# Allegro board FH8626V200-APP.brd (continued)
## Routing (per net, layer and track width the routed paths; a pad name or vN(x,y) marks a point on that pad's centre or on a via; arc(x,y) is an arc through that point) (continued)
CIS_SCL: length 54.2
  TOP w0.102: U14.11 52.02,41.2 51.69,41.53 49.89,41.53 v1(49.86,41.55) ; J3.36 v1(7.48,52.84)
  BOTTOM w0.102: v1(49.86,41.55) 49.63,41.78 R34.2 48.51,42.29 46.56,42.29 46.23,42.62 46.23,43.28 41.78,47.73 12.6,47.73 v1(7.48,52.84)
CIS_SDA: length 54
  TOP w0.102: v1(8.26,52.83) 7.27,51.84 J3.34 ; U14.10 52.18,41.55 51.85,41.88 50.17,41.88 v1(49.78,42.27)
  BOTTOM w0.102: v1(8.26,52.83) 13.03,48.06 41.86,48.06 46.48,43.43 48.51,43.43 R35.2 49.12,42.93 v1(49.78,42.27)
CLK_IN: length 10.8
  TOP w0.203: U14.41 61.05,35.85 61.59,35.3 61.59,27.05 61.09,26.54 R39.2
CLK_OUT: length 11.8
  TOP w0.203: U14.42 61.4,35.97 62,35.36 62,26.39 R40.1 R41.2
DDR_D1.8V: length 9.5
  TOP w0.381: 108.08,35.18 108.08,37.08 108.58,37.59 C27.1 R14.2
DDR_D1.35V: length 10.1
  TOP w0.381: R85.2 C66.1 114.02,31.14 107.72,31.14 107.31,30.73 107.31,28.96
DDR_IO: length 4.2
  TOP w0.178: U14.36 59.3,35.35 59.49,35.15 v1(59.49,34.92) v1(59.94,34.92) ; U14.33 58.24,36.02 57.77,35.55 v1(57.77,35.25) 57.77,34.64 v1(57.78,34.64)
E0_CT1: length 2
  TOP w0.381: U23.2 v1(61.72,65.33)
  BOTTOM w0.381: C165.1 v1(61.72,65.33)
E0_CT2: length 2.1
  TOP w0.381: U23.7 v1(68.07,65.35)
  BOTTOM w0.381: C167.1 v1(68.07,65.35)
EN1: length 25.2
  TOP w0.381: v1(120.02,43.76) 120.02,44.07 121.03,45.09 R13.1
  VCC w0.381: v1(115.82,32.26) 117.47,33.91 v1(117.47,36.96) 117.65,36.96 120.12,39.43 120.12,43.66 v1(120.02,43.76)
  BOTTOM w0.381: R20.1 v1(117.47,36.96) ; R89.1 116.74,29.49 D4.K v1(115.82,32.26) 115.57,32 R19.1 C32.1
EN2: length 5
  TOP w0.381: R12.1 138.79,43.74 v1(139.22,43.74)
  BOTTOM w0.381: D11.K 141.3,44.17 R84.1 C62.1 139.67,44.2 v1(139.22,43.74)
EN3: length 5.5
  BOTTOM w0.381: R27.1 116.84,44.58 116.84,45.75 D5.K 115.57,46.35 115.24,46.02 R22.1 C33.1
EPHY_RXN: length 18.7
  TOP w0.102: U14.67 62.1,46.4 64.01,48.31 64.01,52.32 68.25,56.57 68.25,57.3 68.35,57.4 D32.K 68.36,58.24 68.26,58.34 68.26,58.48 C155.2 68.25,59.13 68.25,59.61 R181.2
EPHY_RXP: length 18.7
  TOP w0.102: R178.2 67.89,59.61 67.89,59.13 C155.1 67.88,58.48 67.88,58.34 D32.A 67.79,57.4 67.89,57.3 67.89,56.71 63.65,52.47 63.65,48.46 61.75,46.55 U14.68
EPHY_TXN: length 16.3
  TOP w0.102: R177.2 61.9,59.61 61.9,59.13 C154.2 61.9,58.47 61.9,58.35 D20.K 62,57.4 61.9,57.3 61.9,47.17 61.4,46.66 U14.69
EPHY_TXP: length 16.3
  TOP w0.102: U14.70 61.05,46.82 61.54,47.32 61.54,57.3 61.44,57.4 D20.A 61.54,58.35 61.54,58.47 C154.1 61.54,59.13 61.54,59.61 R174.2
ETH_ACT: length 22.5
  BOTTOM w0.102: JP4.1 53.76,78.95 70.4,78.95 D19.K 72.01,75.45 J17.12
ETH_STA: length 42.4
  TOP w0.102: v1(50.67,71.88) 50.67,67.11 55.73,62.05 55.73,47.88 56.77,46.84 56.77,46.53 57.19,46.11 U14.81
  BOTTOM w0.102: v1(50.67,71.88) 52.32,73.53 54.74,73.53 55.37,74.17 59.29,74.17 J17.10 60.83,75.71 D23.K
GPIO_0: length 74.9
  TOP w0.102: JP11.2 124.51,54.28 88.6,54.28 72.36,38.05 U14.47
GPIO_1: length 69.7
  TOP w0.102: U14.48 72.25,38.4 88.44,54.58 119.74,54.58 JP12.2
GPIO_2: length 64.4
  TOP w0.102: U14.49 72.15,38.75 88.32,54.91 114.99,54.91 JP7.2
GPIO_3: length 59.8
  TOP w0.102: JP9.2 111.12,56.13 111.12,55.36 111.02,55.25 88.17,55.25 72.01,39.1 64.49,39.1 64.38,38.99 63.68,38.99 63.57,39.1 U14.50
GPIO_4: length 54.1
  TOP w0.102: U14.51 63.68,39.45 63.8,39.32 64.34,39.32 64.47,39.45 71.88,39.45 88.06,55.63 105.54,55.63 JP10.2
GPIO_28: length 34.1
  TOP w0.102: U14.80 57.54,46.44 56.03,47.96 56.03,62.51 55.24,63.3 55.24,74.93 JP4.2
GPIO_RESET: length 70.3
  TOP w0.102: U14.24 55.09,35.95 54.99,35.85 54.99,35.2 54.84,35.05 54.36,35.05 54.18,34.87 54.18,33.45 52.93,32.21 52.93,26.42 53.09,26.26 v1(53.09,25.02) ; v1(102.08,17.86) 103.43,17.86 v1(104.97,16.32)
  VCC w0.102: v1(102.08,17.86) 96.06,17.86 93.52,20.4 65.86,20.4 65.38,19.91 58.55,19.91 53.82,24.64 53.47,24.64 v1(53.09,25.02)
  BOTTOM w0.102: R166.2 104.97,15.81 v1(104.97,16.32)
HOLD: length 48.6
  TOP w0.102: v1(69.98,14.96) 70.21,14.73 U9.7 72.39,14.73 75.69,11.43 78.44,11.43 84.3,5.56 99.8,5.56 101.73,7.49 101.73,8.79 100.72,9.79 U6.7
  BOTTOM w0.102: U10.7 72.24,16 72.42,16.18 72.42,16.48 72.24,16.66 70.33,16.66 70.23,16.56 70.23,15.21 v1(69.98,14.96) 69.62,14.96 69.22,15.37 69.22,16.38
IR_LED_IN: length 3.2
  TOP w0.508: J13.1 v1(7.23,69.48)
  BOTTOM w0.508: 8,70.48 8,69.99 7.49,69.48 v1(7.23,69.48)
IRCUT_OFF: length 152.2
  TOP w0.102: v1(50.29,25.73) v1(8.41,25.73) ; JP10.1 109.88,57.43 109.88,59.94 109.55,60.27 108.25,60.27 103.99,56.01 87.99,56.01 72.06,40.09 71.84,40.09 v1(71.69,39.94) ; v1(74.52,21.31) 82.87,29.66 82.87,37.69 v1(82.2,38.36)
  VCC w0.102: v1(50.29,25.73) 50.65,25.73 50.88,25.96 53.77,25.96 55.4,24.33 62.92,24.33 65.96,21.29 74.5,21.29 v1(74.52,21.31)
  BOTTOM w0.102: v1(82.2,38.36) 81.95,38.61 73.02,38.61 v1(71.69,39.94) ; R144.2 8.38,25.7 v1(8.41,25.73)
IRCUT_ON: length 64.1
  TOP w0.102: U14.25 55.44,35.94 55.27,35.76 55.27,33.81 54.1,32.64 54.1,24.77 53.47,24.13 50.8,24.13 49.71,25.22 5.11,25.22 v1(4.6,25.73)
  BOTTOM w0.102: v1(4.6,25.73) 4.57,25.7 R145.2
IRCUT_OUT_OFF: length 3.3
  TOP w0.508: J15.1 4.56,14.21 v1(4.57,14.22)
  BOTTOM w0.508: U19.4 v1(4.57,14.22)
IRCUT_OUT_ON: length 6.1
  TOP w0.508: J15.2 v1(4.69,12.96)
  BOTTOM w0.508: v1(4.69,12.96) 5.47,12.96 7.11,14.61 U19.2
JTAG_RTCK: length 3.4
  BOTTOM w0.102: R139.1 U18.11
JTAG_SRSTN: length 4.6
  BOTTOM w0.102: U18.15 R141.1 R143.2
LDO_MICBIAS: length 12.3
  VCC w0.381: v1(53.42,16.26) 51.96,17.72 47.56,17.72 v1(47.5,17.65)
  BOTTOM w0.305: R103.2 v1(53.42,16.26)
  BOTTOM w0.381: C112.1 v1(47.5,17.65) C111.1 C110.1 43.82,17.65 43.49,17.97 U11.5
MIPI_CKN: length 47.3
  TOP w0.102: U14.5 53.51,43.3 53.48,43.27 52.74,43.27 52.02,43.99 35.64,43.99 35.13,44.5 25.8,44.5 25.52,44.22 25.52,43.26 25.41,43.15 24.5,43.15 24.4,43.26 24.4,44.22 24.12,44.5 22.95,44.5 22.67,44.22 22.67,43.26 22.57,43.15 21.66,43.15 21.55,43.26 21.55,44.22 21.27,44.5 16.89,44.5 T24.1 16.2,44.5 13.59,44.5 13.25,44.84 J3.19
MIPI_CKP: length 47.3
  TOP w0.102: U14.6 53.5,42.95 53.48,42.97 52.61,42.97 51.89,43.69 35.51,43.69 35.01,44.19 25.92,44.19 25.82,44.09 25.82,43.13 25.54,42.85 24.37,42.85 24.09,43.13 24.09,44.09 23.99,44.19 23.08,44.19 22.98,44.09 22.98,43.13 22.7,42.85 21.53,42.85 21.25,43.13 21.25,44.09 21.15,44.19 16.89,44.19 T23.1 16.2,44.19 13.59,44.19 13.25,43.84 J3.17
MIPI_D5.0V: length 2.7
  TOP w0.381: 14.86,52.84 v1(14.05,52.84) 12.15,52.84
MIPI_DN0: length 47.3
  TOP w0.102: U14.1 53.48,44.7 53.46,44.67 53.32,44.67 51.26,46.74 41.01,46.74 v1(40.84,46.9) ; J3.5 13.25,37.84 13.59,37.5 16.2,37.5 T20.1 16.89,37.5 17.74,37.5 v1(17.9,37.66)
  BOTTOM w0.102: v1(17.9,37.66) 18.07,37.5 30.94,37.5 40.18,46.74 40.68,46.74 v1(40.84,46.9)
MIPI_DN1: length 47.3
  TOP w0.102: U14.4 53.48,43.65 53.46,43.67 52.93,43.67 51.44,45.16 37.55,45.16 37.11,45.6 37.11,46.43 v1(36.94,46.6) ; v1(17.53,40.66) 17.36,40.5 16.89,40.5 T22.1 16.2,40.5 13.59,40.5 13.25,40.84 J3.11
  BOTTOM w0.102: v1(17.53,40.66) 17.69,40.5 31.55,40.5 37.11,46.05 37.11,46.43 v1(36.94,46.6)
MIPI_DP0: length 47.3
  TOP w0.102: v1(17.9,37.03) 17.74,37.19 16.89,37.19 T19.1 16.2,37.19 13.59,37.19 13.25,36.84 J3.3 ; U14.2 53.49,44.35 53.47,44.37 53.19,44.37 51.13,46.43 41.01,46.43 v1(40.84,46.27)
  BOTTOM w0.102: v1(40.84,46.27) 40.68,46.43 40.31,46.43 31.07,37.19 18.07,37.19 v1(17.9,37.03)
MIPI_DP1: length 47.3
  TOP w0.102: v1(37.58,46.6) 37.41,46.43 37.41,45.73 37.68,45.47 51.56,45.47 53.05,43.97 53.47,43.97 53.5,44 U14.3 ; J3.9 13.25,39.84 13.59,40.19 16.2,40.19 T21.1 16.89,40.19 17.36,40.19 v1(17.53,40.03)
  BOTTOM w0.102: v1(37.58,46.6) 37.41,46.43 37.41,45.92 31.68,40.19 17.69,40.19 v1(17.53,40.03)
MOTO_OUT_2: length 9.4
  TOP w0.102: v1(112.39,79.38) 112.39,77.6 112.23,77.43 U26.16 ; R150.1 v1(108.08,80.95)
  BOTTOM w0.102: v1(112.39,79.38) 111.9,79.38 111.16,78.64 109.76,78.64 109.27,79.13 109.27,79.52 108.08,80.72 v1(108.08,80.95)
MOTO_OUT_3: length 7.5
  TOP w0.102: v1(108.92,81.79) 108.92,83.06 109.36,83.5 J19.2 ; U26.2 110.05,79.45 v1(110.11,79.5)
  BOTTOM w0.102: v1(110.11,79.5) 110.11,80.52 108.92,81.71 v1(108.92,81.79)
MOTO_OUT_4: length 6.6
  TOP w0.102: R151.1 109.96,81.79 107.24,79.07 107.24,77.6 107.41,77.43 U26.5
MOTO_OUT_5: length 8.9
  TOP w0.102: J19.4 111.86,80.87 111.51,80.52 109.73,80.52 109.4,80.19 U26.3
MOTO_OUT_6: length 8.4
  TOP w0.102: R152.1 v1(120.78,80.64) ; v1(125.45,78.84) 125.7,78.59 125.7,77.7 125.44,77.43 U27.16
  BOTTOM w0.102: v1(120.78,80.64) 123.65,80.64 v1(125.45,78.84)
MOTO_OUT_7: length 9.4
  TOP w0.102: J20.2 121.93,81.52 v1(122.05,81.41) ; U27.2 123.52,79.57 124.31,80.37 v1(124.31,81.33)
  BOTTOM w0.102: v1(124.31,81.33) 124.28,81.33 124.21,81.41 v1(122.05,81.41)
MOTO_OUT_8: length 5.7
  TOP w0.102: U27.5 120.82,77.43 120.65,77.6 120.65,78.61 123.06,81.03 R153.1
MOTO_OUT_9: length 7.5
  TOP w0.102: U27.3 122.86,79.55 123.66,80.35 123.66,81.32 124.43,82.08 J20.4
NAND_CS: length 24.3
  TOP w0.102: v1(80.9,17.27) 81.92,17.27 82.3,16.89 82.3,14.48 84.2,12.57 v1(84.84,12.57) 89.55,12.57 U6.1
  BOTTOM w0.102: v1(84.84,12.57) 82.55,10.29 JP14.3 ; U10.1 v1(80.9,17.27) 81.03,17.27 R59.2
NOR_CS: length 12.7
  TOP w0.102: v1(80.67,12.95) 80.16,13.46 U9.1
  BOTTOM w0.102: v1(80.67,12.95) 80.92,12.7 R52.2 81.53,12.04 80.92,11.43 74.02,11.43 JP14.1
PHY_RN: length 11.6
  TOP w0.102: U23.9 69.34,73.28 68.2,74.42 68.2,74.96 64.44,78.71 64.44,79.2 64.59,79.35 66.34,79.35 66.65,79.66 J17.6
PHY_RP: length 11.6
  TOP w0.102: U23.11 66.8,73.41 67.84,74.45 67.84,74.81 64.08,78.57 64.08,79.35 63.59,79.84 J17.3
PHY_TN: length 10.7
  TOP w0.102: U23.14 62.99,73.46 61.95,74.5 61.95,77.47 60.91,78.51 60.91,79.93 61.92,80.95 62.26,80.95 62.57,80.64 J17.2
PHY_TP: length 10.7
  TOP w0.102: J17.1 61.55,81.08 60.55,80.08 60.55,78.36 61.59,77.32 61.59,74.55 60.45,73.41 U23.16
PWM11: length 71.6
  TOP w0.102: R108.1 20.55,22.61 22.2,24.26 49.33,24.26 v1(49.63,23.95)
  VCC w0.102: JP22.3 83.31,23.37 64.9,23.37 61.85,26.42 50.34,26.42 49.66,25.73 49.66,23.98 v1(49.63,23.95)
PWM_2: length 68.4
  TOP w0.102: U14.55 71.63,40.85 94,63.22 99.95,63.22 107.64,70.9 111.42,70.9 112.27,71.75 v1(112.27,74.17) ; v1(113.28,74.68) 113.28,75.31 112.47,76.13 U26.14
  BOTTOM w0.102: v1(112.27,74.17) 112.78,74.68 v1(113.28,74.68)
PWM_3: length 67.4
  TOP w0.102: U14.54 71.86,40.5 94.13,62.76 94.23,62.87 100.33,62.87 107.8,70.33 111.73,70.33 112.7,71.3 112.7,74.95 112.17,75.48 U26.13
PWM_4: length 61.4
  TOP w0.102: U14.57 71.13,41.55 93.49,63.92 98.84,63.92 106.43,71.5 106.43,75.34 107.21,76.13 U26.7
PWM_5: length 61.4
  TOP w0.102: U14.56 71.35,41.2 93.72,63.57 99.38,63.57 106.96,71.15 106.96,75.08 107.36,75.48 U26.8
PWM_6: length 22
  TOP w0.102: v1(126.89,67.42) 126.89,75.31 126.07,76.13 U27.14
  BOTTOM w0.102: JP11.1 126.89,58.66 v1(126.89,67.42)
PWM_7: length 20.8
  TOP w0.102: U27.13 125.82,75.48 126.24,75.06 v1(126.24,68.07)
  BOTTOM w0.102: JP12.1 126.24,58.55 v1(126.24,68.07)
PWM_8: length 21.5
  TOP w0.102: U27.7 120.71,76.13 119.95,75.37 119.95,66.23 v1(120.4,65.79)
  BOTTOM w0.102: v1(120.4,65.79) 120.52,65.66 120.52,57.91 JP7.1
PWM_9: length 22.7
  TOP w0.102: U27.8 120.94,75.48 120.65,75.18 v1(120.65,67.06)
  BOTTOM w0.102: v1(120.65,67.06) 120.04,67.06 115.82,62.84 115.82,58.29 JP9.1
RESETN: length 68.3
  TOP w0.102: U14.43 61.75,36.04 62.64,35.15 63.14,35.15 63.75,34.54 v1(63.75,33.02) 63.75,31.01 65.94,28.83 65.94,22.86 v1(66.55,22.25) ; v1(114.55,17.53) 106.55,17.53 105.08,19 v1(102.41,19)
  VCC w0.102: v1(66.55,22.25) 66.57,22.23 79.63,22.23 80.75,21.11 91.16,21.11 91.62,21.56 95.94,21.56 98.5,19 v1(102.41,19)
  BOTTOM w0.102: v1(63.75,33.02) 63.88,33.15 C190.2 ; v1(114.55,17.53) R172.2
RTC_VBAT: length 14.7
  BOTTOM w0.381: R61.1 C102.1 69.47,34.04 68.83,34.67 64.9,34.67
RTC_XIN: length 12.5
  TOP w0.203: U14.45 63.29,37.35 64.44,36.2 72.9,36.2 C79.2 73.46,36 U8.1
RTC_XOUT: length 12.4
  TOP w0.203: U8.4 73.34,36.9 C81.2 73.03,36.7 64.47,36.7 63.47,37.7 U14.46
SD0_3.3V: length 28.8
  TOP w0.381: J4.6 v1(35.26,61.09)
  BOTTOM w0.381: 37.72,62.1 37.29,62.1 36.27,61.09 v1(35.26,61.09) ; 37.72,62.1 R67.1 ; 37.72,62.1 37.47,62.36 37.47,62.87 36.83,63.5 31.62,63.5 30.86,62.74 R82.1 R64.1 R65.1 ; R67.1 C104.1 R74.2 43.69,64.14 MQ1.3 ; R67.1 R66.1
SD0_CD: length 65.6
  TOP w0.102: v1(45.69,62.08) 45.11,62.08 44.93,61.9 34.44,61.9 v1(34.11,61.57) ; U14.88 54.74,45.85 54.47,46.12 53.83,46.12 52.34,47.61 52.34,49.82 51.79,50.37 51.79,52.48 48.95,55.32 46.02,55.32 44.2,53.49 40.39,53.49 40.18,53.7 37.13,53.7 36.8,54.03 36.8,55.55 36.68,55.68 36.23,55.68 36.13,55.58 36.13,54.91 36.03,54.81 35.83,54.81 35.72,54.91 35.72,55.58 35.62,55.68 35.42,55.68 35.32,55.58 35.32,54.91 35.22,54.81 35.01,54.81 34.91,54.91 34.91,55.58 34.81,55.68 34.61,55.68 34.5,55.58 34.5,54.91 34.4,54.81 34.2,54.81 34.1,54.91 34.1,55.58 34,55.68 33.79,55.68 33.69,55.58 33.69,54.91 33.59,54.81 33.39,54.81 33.29,54.91 33.29,55.58 33.18,55.68 32.87,55.68 32.64,55.91 v1(32.64,57.38)
  BOTTOM w0.102: v1(45.69,62.08) 45.69,62.66 46.08,63.04 46.08,64.8 45.47,65.41 45.47,67.56 46.35,68.45 R75.1 ; v1(34.11,61.57) 34.11,59.39 33.66,58.93 R77.1 v1(32.64,57.38)
SD0_CLK: length 37.3
  TOP w0.102: v1(37.72,57.15) 38.15,56.72 38.15,54.53 38.25,54.43 38.46,54.43 38.56,54.53 38.56,55.27 38.66,55.37 38.86,55.37 38.96,55.27 38.96,54.53 39.07,54.43 39.27,54.43 39.37,54.53 39.37,55.27 39.47,55.37 39.67,55.37 39.78,55.27 39.78,54.53 39.88,54.43 40.08,54.43 40.18,54.53 40.18,55.27 40.28,55.37 40.49,55.37 40.59,55.27 40.59,54.53 40.69,54.43 40.89,54.43 41,54.53 41,55.27 41.1,55.37 41.3,55.37 41.4,55.27 41.4,54.53 41.5,54.43 41.71,54.43 41.81,54.53 41.81,55.27 41.91,55.37 42.11,55.37 42.21,55.27 42.21,54.53 42.32,54.43 42.52,54.43 42.62,54.53 42.62,55.27 42.72,55.37 42.93,55.37 43.03,55.27 43.03,54.53 43.13,54.43 43.33,54.43 43.43,54.53 43.43,55.27 43.54,55.37 43.74,55.37 43.84,55.27 43.84,54.53 43.94,54.43 44.15,54.43 44.25,54.53 44.25,55.27 44.35,55.37 45.21,55.37 45.62,55.78 50.01,55.78 52.7,53.09 v1(52.7,50.55)
  BOTTOM w0.102: v1(52.7,50.55) C178.1 R204.1 ; R72.1 v1(37.72,57.15)
SD0_CMD: length 40.6
  TOP w0.102: v1(30.86,57.89) 33.26,57.89 33.36,57.78 33.36,57.2 33.46,57.1 33.67,57.1 33.77,57.2 33.77,57.78 33.87,57.89 34.07,57.89 34.18,57.78 34.18,57.2 34.28,57.1 34.48,57.1 34.58,57.2 34.58,57.78 34.68,57.89 34.89,57.89 34.99,57.78 34.99,57.2 35.09,57.1 35.29,57.1 35.39,57.2 35.39,57.78 35.5,57.89 35.7,57.89 35.8,57.78 35.8,57.2 35.9,57.1 36.11,57.1 36.21,57.2 36.21,57.78 36.31,57.89 38.66,57.89 38.91,57.63 38.91,56.34 39.01,56.24 51.13,56.24 53.65,53.72 53.65,47.88 55.44,46.08 U14.86
  BOTTOM w0.102: R79.1 v1(30.86,57.89)
SD0_DATA_0: length 40.3
  TOP w0.102: v1(41.94,57.89) 39.58,57.89 39.34,57.66 39.34,56.67 39.55,56.46 39.82,56.46 39.92,56.57 39.92,57.18 40.02,57.28 40.23,57.28 40.33,57.18 40.33,56.57 40.43,56.46 40.63,56.46 40.73,56.57 40.73,57.18 40.84,57.28 41.04,57.28 41.14,57.18 41.14,56.57 41.24,56.46 41.44,56.46 41.55,56.57 41.55,57.18 41.65,57.28 41.85,57.28 41.95,57.18 41.95,56.57 42.05,56.46 42.26,56.46 42.36,56.57 42.36,57.18 42.46,57.28 42.66,57.28 42.77,57.18 42.77,56.57 42.87,56.46 43.07,56.46 43.17,56.57 43.17,57.18 43.27,57.28 43.48,57.28 43.58,57.18 43.58,56.57 43.68,56.46 51.44,56.46 54.36,53.54 54.36,53.34 54.25,53.24 54.08,53.24 53.98,53.14 53.98,52.93 54.08,52.83 54.25,52.83 54.36,52.73 54.36,52.53 54.25,52.43 54.08,52.43 53.98,52.33 53.98,52.12 54.08,52.02 54.25,52.02 54.36,51.92 54.36,51.72 54.25,51.61 54.08,51.61 53.98,51.51 53.98,51.31 54.08,51.21 54.25,51.21 54.36,51.11 54.36,50.9 54.25,50.8 54.08,50.8 53.98,50.7 53.98,50.5 54.08,50.39 54.25,50.39 54.36,50.29 54.36,50.09 54.25,49.99 54.08,49.99 53.98,49.89 53.98,49.68 54.08,49.58 54.25,49.58 54.36,49.48 54.36,49.28 54.25,49.18 54.08,49.18 53.98,49.07 53.98,48.87 54.08,48.77 54.25,48.77 54.36,48.67 54.36,48.46 54.25,48.36 54.08,48.36 53.98,48.26 53.98,48.06 54.08,47.96 54.25,47.96 54.36,47.85 54.36,47.57 55.45,46.48 55.45,46.38 55.79,46.03 U14.85
  BOTTOM w0.102: R68.1 41.91,57.94 41.94,57.91 v1(41.94,57.89)
SD0_DATA_1: length 40.2
  TOP w0.102: U14.84 56.14,46.04 55.8,46.38 55.8,46.48 54.66,47.62 54.66,53.73 51.58,56.82 50.7,56.82 50.62,56.9 50.62,57.77 50.5,57.89 50.18,57.89 50.08,57.79 50.08,56.82 49.98,56.72 49.78,56.72 49.68,56.82 49.68,57.79 49.57,57.89 49.37,57.89 49.27,57.79 49.27,56.82 49.17,56.72 48.96,56.72 48.86,56.82 48.86,57.79 48.76,57.89 48.56,57.89 48.46,57.79 48.46,56.82 48.35,56.72 48.15,56.72 48.05,56.82 48.05,57.79 47.95,57.89 47.75,57.89 47.64,57.79 47.64,56.82 47.54,56.72 47.34,56.72 47.24,56.82 47.24,57.79 47.14,57.89 46.93,57.89 46.83,57.79 46.83,56.82 46.73,56.72 46.53,56.72 46.42,56.82 46.42,57.79 46.32,57.89 46.12,57.89 46.02,57.79 46.02,56.82 45.92,56.72 45.71,56.72 45.61,56.82 45.61,57.79 45.51,57.89 45.31,57.89 45.21,57.79 45.21,56.82 45.1,56.72 44.9,56.72 44.8,56.82 44.8,57.79 44.7,57.89 44.49,57.89 44.39,57.79 44.39,56.82 44.29,56.72 44.09,56.72 43.99,56.82 43.99,57.79 43.88,57.89 v1(43.48,57.89)
  BOTTOM w0.102: v1(43.48,57.89) 43.48,58.06 43.56,58.14 R69.1
SD0_DATA_2: length 40.7
  TOP w0.102: v1(25.91,58.17) 26.07,58.32 50.57,58.32 54.93,53.96 54.93,47.82 56.11,46.63 56.11,46.48 56.49,46.1 U14.83
  BOTTOM w0.102: R70.1 v1(25.91,58.17)
SD0_DATA_3: length 40.7
  TOP w0.102: v1(29.21,58.8) 29.34,58.67 50.65,58.67 50.82,58.51 50.96,58.51 51.13,58.68 51.28,58.68 51.42,58.53 51.42,58.39 51.25,58.22 51.25,58.07 51.39,57.93 51.53,57.93 51.71,58.1 51.85,58.1 52,57.96 52,57.82 51.82,57.64 51.82,57.5 51.97,57.35 52.11,57.35 52.28,57.53 52.43,57.53 52.57,57.38 52.57,57.24 52.4,57.07 52.4,56.92 52.54,56.78 52.68,56.78 52.86,56.95 53,56.95 53.15,56.81 53.15,56.67 52.97,56.49 52.97,56.35 55.24,54.08 55.24,47.96 56.44,46.76 56.44,46.46 56.84,46.05 U14.82
  BOTTOM w0.102: v1(29.21,58.8) 29.08,58.93 R71.1
SD0_EN: length 8.3
  BOTTOM w0.102: JP4.3 50.04,72.52 R80.1 R78.1
SPI0_CLK: length 84.3
  TOP w0.102: v1(55.24,32.38) 55.07,32.21 55.07,18.85 57.91,16 62.39,16 62.49,15.9 62.49,14.92 62.59,14.82 62.9,14.82 63,14.92 63,15.9 63.1,16 63.41,16 63.51,15.9 63.51,14.92 63.61,14.82 63.92,14.82 64.02,14.92 64.02,15.9 64.12,16 64.42,16 64.52,15.9 64.52,14.92 64.63,14.82 64.93,14.82 65.03,14.92 65.03,15.9 65.13,16 65.44,16 65.54,15.9 65.54,14.92 65.64,14.82 65.95,14.82 66.05,14.92 66.05,15.9 66.15,16 66.46,16 66.56,15.9 66.56,14.92 66.66,14.82 66.96,14.82 67.06,14.92 67.06,15.9 67.17,16 67.47,16 67.57,15.9 67.57,14.92 67.67,14.82 67.98,14.82 68.08,14.92 68.08,15.9 68.18,16 U9.6 72.59,16 v1(73.13,15.47) 76.4,12.19 79.04,12.19 84.49,6.74 87.85,6.74 88.09,6.5 95.94,6.5 96.19,6.25 99.26,6.25 100.54,7.53 U6.6
  BOTTOM w0.102: R203.1 v1(55.24,32.38) C177.1 ; 69.22,14.35 70.51,14.35 70.89,14.73 U10.6 72.39,14.73 v1(73.13,15.47)
SPI0_CSN_0: length 40
  TOP w0.102: U14.27 56.14,35.79 56.34,35.6 56.34,33.12 56.77,32.69 56.77,19.07 v1(58.72,17.12) ; JP14.2 73.77,11.94 65.15,11.94 v1(63.75,13.34)
  VCC w0.102: v1(58.72,17.12) 62.51,13.34 v1(63.75,13.34)
SPI0_D_2: length 43.5
  TOP w0.102: U14.30 57.19,35.99 57.07,35.86 57.07,34.19 59.33,31.93 59.33,19.91 61.47,17.78 66.42,17.78 66.8,18.16 79.76,18.16 80.39,17.53 80.39,16.54 v1(80.7,16.23)
  BOTTOM w0.102: v1(80.7,16.23) 81.94,16.23 R51.1
SPI0_D_3: length 44
  TOP w0.102: U14.31 57.54,35.95 57.33,35.74 57.33,34.44 59.66,32.11 59.66,31.33 59.77,31.23 60.43,31.23 60.53,31.13 60.53,30.92 60.43,30.82 59.77,30.82 59.66,30.72 59.66,30.52 59.77,30.42 60.43,30.42 60.53,30.31 60.53,30.11 60.43,30.01 59.77,30.01 59.66,29.91 59.66,29.7 59.77,29.6 60.43,29.6 60.53,29.5 60.53,29.3 60.43,29.2 59.77,29.2 59.66,29.09 59.66,28.89 59.77,28.79 60.43,28.79 60.53,28.69 60.53,28.49 60.43,28.38 59.77,28.38 59.66,28.28 59.66,28.08 59.77,27.98 60.43,27.98 60.53,27.88 60.53,27.67 60.43,27.57 59.77,27.57 59.66,27.47 59.66,20.22 61.66,18.22 62.21,18.22 62.32,18.33 62.32,19.33 62.42,19.43 62.62,19.43 62.72,19.33 62.72,18.33 62.82,18.22 63.03,18.22 63.13,18.33 63.13,19.33 63.23,19.43 63.43,19.43 63.53,19.33 63.53,18.33 63.64,18.22 63.84,18.22 63.94,18.33 63.94,19.33 64.04,19.43 64.25,19.43 64.35,19.33 64.35,18.33 64.45,18.22 64.65,18.22 64.75,18.33 64.75,19.33 64.86,19.43 65.06,19.43 65.16,19.33 65.16,18.33 65.26,18.22 v1(65.77,18.22)
  BOTTOM w0.102: R58.2 67.69,16.89 66.45,16.89 66.19,17.14 66.19,17.81 v1(65.77,18.22)
SPI0_RXD: length 90.1
  TOP w0.102: U6.2 89.13,10.62 88.13,11.63 87.75,11.63 87.65,11.52 87.65,8.97 87.54,8.87 87.24,8.87 87.14,8.97 87.14,11.52 87.04,11.63 86.73,11.63 86.63,11.52 86.63,8.97 86.53,8.87 86.22,8.87 86.12,8.97 86.12,11.52 86.02,11.63 85.72,11.63 85.61,11.52 85.61,8.97 85.51,8.87 85.21,8.87 85.11,8.97 85.11,11.52 85,11.63 84.7,11.63 84.6,11.52 84.6,8.97 84.5,8.87 84.19,8.87 84.09,8.97 84.09,11.52 83.99,11.63 82.85,11.63 82.73,11.75 82.73,12.78 81.41,14.1 80.72,14.1 80.09,14.73 U9.2 78.41,14.73 77.72,15.42 v1(77.72,16) 75.95,17.78 67.18,17.78 66.85,17.45 61.19,17.45 58.95,19.68 58.95,28.44 58.85,28.54 58.04,28.54 57.94,28.64 57.94,28.82 58.06,28.94 58.85,28.94 58.95,29.05 58.95,29.25 58.85,29.35 58.04,29.35 57.94,29.45 57.94,29.63 58.06,29.76 58.85,29.76 58.95,29.86 58.95,30.06 58.85,30.16 58.04,30.16 57.94,30.27 57.94,30.44 58.06,30.57 58.85,30.57 58.95,30.67 58.95,30.88 58.85,30.98 58.04,30.98 57.94,31.08 57.94,31.26 58.06,31.38 58.85,31.38 58.95,31.48 58.95,31.8 56.84,33.91 U14.29
  BOTTOM w0.102: R53.2 80.54,16.76 79.78,16 U10.2 78.92,16 78.56,16.36 78.56,18.14 78.44,18.26 77.98,18.26 77.88,18.16 77.88,16.15 v1(77.72,16)
SPI0_TXD: length 92
  TOP w0.102: U14.28 56.49,35.81 56.59,35.71 56.59,33.53 57.28,32.84 57.28,28.26 57.38,28.16 58.04,28.16 58.14,28.06 58.14,27.86 58.04,27.76 57.38,27.76 57.28,27.65 57.28,27.45 57.38,27.35 58.04,27.35 58.14,27.25 58.14,27.05 58.04,26.94 57.38,26.94 57.28,26.84 57.28,26.64 57.38,26.54 58.04,26.54 58.14,26.44 58.14,26.23 58.04,26.13 57.38,26.13 57.28,26.03 57.28,25.83 57.38,25.72 58.04,25.72 58.14,25.62 58.14,25.42 58.04,25.32 57.38,25.32 57.28,25.22 57.28,25.01 57.38,24.91 58.04,24.91 58.14,24.81 58.14,24.61 58.04,24.51 57.38,24.51 57.28,24.4 57.28,24.2 57.38,24.1 58.04,24.1 58.14,24 58.14,23.79 58.04,23.69 57.38,23.69 57.28,23.59 57.28,23.39 57.38,23.29 58.04,23.29 58.14,23.18 58.14,22.98 58.04,22.88 57.38,22.88 57.28,22.78 57.28,22.57 57.38,22.47 58.04,22.47 58.14,22.37 58.14,22.17 58.04,22.07 57.38,22.07 57.28,21.97 57.28,21.76 57.38,21.66 58.04,21.66 58.14,21.56 58.14,21.36 58.04,21.25 57.38,21.25 57.28,21.15 57.28,20.95 57.38,20.85 58.04,20.85 58.14,20.75 58.14,20.54 58.04,20.44 57.38,20.44 57.28,20.34 57.28,19.84 60.09,17.02 v1(65.51,17.02) 67.18,17.02 67.36,16.84 70.18,16.84 70.61,17.27 U9.5 72.64,17.27 77.06,12.85 79.5,12.85 80.79,11.56 81.05,11.56 84.35,8.26 89.79,8.26 90.49,7.56 92.84,7.56 92.94,7.66 92.94,7.98 93.05,8.08 93.25,8.08 93.35,7.98 93.35,7.66 93.45,7.56 93.65,7.56 93.76,7.66 93.76,7.98 93.86,8.08 94.06,8.08 94.16,7.98 94.16,7.66 94.26,7.56 94.47,7.56 94.57,7.66 94.57,7.98 94.67,8.08 94.87,8.08 94.98,7.98 94.98,7.66 95.08,7.56 95.28,7.56 95.38,7.66 95.38,7.98 95.48,8.08 95.69,8.08 95.79,7.98 95.79,7.66 95.89,7.56 98.32,7.56 U6.5
  BOTTOM w0.102: v1(65.51,17.02) 65.28,17.02 64.77,16.51 64.77,15.49 67.44,12.83 68.71,12.83 69.34,13.46 U10.5
UART0_RX: length 103.8
  TOP w0.102: v1(51.08,25.02) 51.08,25.25 51.61,25.78 51.61,32.31 53.09,33.78 53.09,36.8 53.63,37.35 U14.22 ; v1(125.35,7.15) 122.81,4.61 122.81,2.41 121.92,1.52 113.54,1.52 112.14,2.92 112.14,3.17 104.01,11.3 104.01,13.08 101.52,15.57 95.38,15.57 92.96,17.98 90.35,17.98 v1(89.79,18.54)
  VCC w0.102: v1(51.08,25.02) 51.08,24.89 56.95,19.02 89.31,19.02 v1(89.79,18.54)
  BOTTOM w0.102: R127.1 v1(125.35,7.15) R122.1
UART0_TX: length 105.7
  TOP w0.102: v1(51.69,25.02) 51.69,25.27 51.99,25.58 51.99,32.18 53.49,33.68 53.49,35.43 54.03,35.97 54.61,35.97 54.74,36.1 U14.23 ; v1(90.37,18.72) 92.99,18.72 95.76,15.95 101.9,15.95 104.52,13.34 104.52,11.56 112.01,4.06 113.54,4.06 115.7,1.91 121.41,1.91 122.17,2.67 122.17,4.7 125.09,7.62 125.86,7.62 126.36,7.11 v1(128.65,7.11)
  VCC w0.102: v1(90.37,18.72) 89.79,19.3 57.4,19.3 v1(51.69,25.02)
  BOTTOM w0.102: R124.1 v1(128.65,7.11) R125.1
UART1_RX: length 31.2
  TOP w0.102: U15.8 112.14,7.37 102.77,16.74 97,16.74 91.14,22.61 JP22.1
UART1_TX: length 73.9
  TOP w0.102: v1(71.88,43.69) 71.75,43.69 70.31,42.25 66.14,42.25 66.03,42.14 65.07,42.14 64.97,42.25 U14.59 ; U15.6 102.92,17.22 97.17,17.22 85.6,28.79 85.6,37.94 v1(80.29,43.26)
  BOTTOM w0.102: v1(71.88,43.69) 72.19,43.99 79.55,43.99 v1(80.29,43.26)
USB_DM: length 42.1
  TOP w0.114: v1(88.22,66.06) 88.39,65.88 88.39,65.41 70.87,47.88 69.09,47.88 67.84,46.63 65.91,46.63 63.6,44.32 63.44,44.32 63.41,44.35 U14.65 ; v1(91.44,69.13) 91.27,68.96 90.93,68.96 90.76,69.13 90.76,69.68 R146.1
  BOTTOM w0.114: v1(88.22,66.06) 88.4,66.24 88.4,66.55 89.71,67.86 89.71,68.02 89.6,68.13 89.6,68.29 89.77,68.46 89.93,68.46 90.04,68.35 90.2,68.35 90.81,68.96 91.27,68.96 v1(91.44,69.13)
USB_DP: length 42.1
  TOP w0.114: v1(91.44,68.5) 91.27,68.67 90.81,68.67 90.47,69.01 90.47,69.68 R147.1 ; v1(88.86,66.06) 88.68,65.88 88.68,65.28 70.99,47.59 69.21,47.59 67.96,46.34 66.03,46.34 63.72,44.03 63.41,44.03 63.38,44 U14.64
  BOTTOM w0.114: v1(91.44,68.5) 91.27,68.67 90.93,68.67 88.69,66.43 88.69,66.22 v1(88.86,66.06)
USB_PWREN: length 46.4
  TOP w0.102: v1(98.04,67.44) 96.77,66.17 93.65,66.17 70.87,43.39 67.92,43.39 67.13,42.6 66.17,42.6 65.94,42.37 65.25,42.37 65.02,42.6 U14.60
  BOTTOM w0.102: R162.1 v1(98.04,67.44)
USB_VBUS: length 48.7
  TOP w0.178: U14.62 64.18,43.3 64.82,43.94 65.05,43.94
  TOP w0.508: 65.05,43.94 v1(65.07,43.94) 66.65,43.94 67.49,44.78 68.58,44.78 69.27,45.47 71.12,45.47 96.9,71.25 v1(96.9,72.39)
  BOTTOM w0.201: C196.2 64.94,44.07 v1(65.07,43.94)
  BOTTOM w0.508: R158.2 v1(96.9,72.39)
USBN: length 5.1
  TOP w0.114: R146.2 90.76,71.55 90.76,71.84 D13.A 90.79,72.66 90.79,72.93 91.69,73.84 J21.2
USBP: length 5
  TOP w0.114: J21.3 89.69,73.81 90.47,73.03 90.47,72.69 90.04,72.26 90.47,71.84 90.47,71.55 R147.2
VM: length 10.1
  TOP w0.254: C187.2 v1(109.6,71.88) ; U26.10 v1(109.4,73.48) ; R211.1 v1(114.05,75.06) ; C182.2 v1(122.94,71.88) ; R207.1 v1(127.76,74.8) ; U27.10 v1(122.86,73.59) ; R208.1 v1(119.38,74.8) ; R209.1 v1(105.41,74.8)
  BOTTOM w0.254: C181.2 122.81,73.53 v1(122.86,73.59) 122.94,73.66 C183.2 ; C184.2 109.4,74.22 v1(109.4,73.48) 109.4,72.84 C185.2
  vias: v1(116.33,75.06) v1(116.97,75.06) v1(117.6,75.06)
WP: length 23.4
  TOP w0.102: U9.3 79.78,16 80.9,14.88 v1(80.9,14.73) 81.46,14.73 84.13,12.05 88.4,12.05 91.05,9.4 U6.3
  BOTTOM w0.102: U10.3 79.88,14.73 80.01,14.61 80.01,13.97 80.52,13.46 82.06,13.46 82.16,13.56 82.16,13.88 82.02,14.02 80.87,14.02 80.77,14.12 80.77,14.61 v1(80.9,14.73) 81.28,14.73 81.41,14.61 R55.2 R51.2
XAIN0_SADC: length 80.2
  TOP w0.102: U14.12 51.74,40.85 v1(51.56,41.02)
  BOTTOM w0.102: v1(51.56,41.02) 51.56,43.31 C97.1 51.69,44.45 51.69,45.62 50.52,46.79 45.92,46.79 42.29,50.42 18.8,50.42 16.7,52.51 16.7,57.78 15.37,59.12 15.37,74.93 JP29.1 JP30.1 J14.1
XAIN1_SADC: length 111.7
  TOP w0.102: U14.13 51.33,40.5 50.88,40.94 v1(50.88,40.97)
  BOTTOM w0.102: J14.2 14.86,85.34 14.86,59.05 16.26,57.66 16.26,52.32 18.53,50.05 42.12,50.05 45.72,46.46 50.42,46.46 51.36,45.52 51.36,44.5 C44.1 51.26,43.48 51.26,41.35 v1(50.88,40.97) 47.45,40.97 47.14,40.67 47.14,40.39 46.99,40.23 44.42,40.23 35.94,31.75 JP20.1
N00509: length 6.6
  BOTTOM w0.381: R129.1 R132.2 C149.1 12.7,66.24 D12.K
N00760: length 3.2
  TOP w0.102: J4.9 v1(42.69,61.09)
  BOTTOM w0.102: R68.2 41.91,61.09 v1(42.69,61.09)
N00772: length 3.3
  TOP w0.102: J4.10 v1(44.39,61.09)
  BOTTOM w0.102: v1(44.39,61.09) 43.56,61.09 R69.2
N00784: length 3.1
  TOP w0.102: J4.1 v1(25.26,61.09)
  BOTTOM w0.102: R70.2 25.91,61.09 v1(25.26,61.09)
N00796: length 3.1
  TOP w0.102: J4.2 v1(27.76,61.09)
  BOTTOM w0.102: v1(27.76,61.09) 28.45,61.09 R71.2
N00808: length 2.5
  TOP w0.102: J4.7 v1(37.76,61.09)
  BOTTOM w0.102: v1(37.76,61.09) 37.72,61.05 R72.2
N00832: length 3.2
  TOP w0.102: J4.4 v1(31.91,61.09)
  BOTTOM w0.102: R77.2 32.64,61.09 v1(31.91,61.09)
N00844: length 3.1
  TOP w0.102: J4.3 v1(30.26,61.09)
  BOTTOM w0.102: v1(30.26,61.09) 30.86,61.09 R79.2
N04317: length 2.5
  BOTTOM w0.508: R144.1 U19.8
N04321: length 2.5
  BOTTOM w0.508: R145.1 U19.5
N04628: length 2.9
  BOTTOM w0.102: R127.2 D9.K 126.36,3.87 126.55,3.68
N04632: length 2.9
  BOTTOM w0.102: J12.3 127.64,3.85 D10.K R125.2
N05813: length 2.8
  BOTTOM w0.201: C146.2 RF2.2 RF1.1
N05817: length 4.6
  BOTTOM w0.201: CN5.1 30.73,8.26 C147.1 RF1.2
N06013: length 12.1
  BOTTOM w0.102: S1.2 117.99,13.46 111.25,13.46 109.86,14.86 R164.2 R165.1
N06017: length 2.8
  BOTTOM w0.102: R166.1 C161.1 R165.2
N06505: length 7.6
  BOTTOM w0.102: R171.2 R172.1 R168.1 C164.1 C163.1 S2.2
N06945: length 3.1
  BOTTOM w0.102: R171.1 114.94,16 R173.2 R170.2
N06949: length 3
  BOTTOM w0.102: R170.1 111.8,14.99 111.7,15.09 U22.2
N07170: length 4.9
  BOTTOM w0.102: U22.3 112.53,19.81 C162.1 R167.2 R169.2
N08491: length 3.7
  BOTTOM w0.508: R101.2 C99.2 R159.1 105.28,72.77 105.33,72.82 MQ3.1
N08611: length 1.7
  BOTTOM w0.381: Q4.1 101.65,67.39 R163.2
N08717: length 2.8
  BOTTOM w0.381: R162.2 R161.1 R163.1
N08811: length 3.7
  BOTTOM w0.102: Q1.3 46.65,67.44 R75.2 R76.1
N09072: length 1.7
  TOP w0.381: D3.A v1(135.13,15.37)
  BOTTOM w0.381: R1.1 v1(135.13,15.37)
N09124: length 4
  BOTTOM w0.508: MQ1.1 47.29,65.28 R76.2 R73.1 C96.2
N09603: length 1.9
  TOP w0.381: C1.1 133.6,28.57 133.28,28.25 U1.1
N09899: length 6
  TOP w0.381: C8.1 R3.2 127.38,27.43 126.49,28.32 126.49,30.86
N09903: length 4.6
  TOP w0.381: U1.3 130.87,26.36 R5.2 C8.2 R3.1
N11558: length 5.8
  TOP w0.381: U2.1 137.28,39.44 C20.2 R8.2 R7.2 R12.2
N12324: length 9.9
  TOP w0.305: R6.2 C13.1 127.36,37.59 127.05,37.9 127.05,45.34
N12328: length 5.1
  TOP w0.381: U2.5 131.82,39.44 R9.2 R6.1 C13.2
N12968: length 3.1
  BOTTOM w0.508: R133.1 R134.1 6.99,72.84 Q3.1
N13141: length 5.1
  BOTTOM w0.102: Q3.3 8.68,75.14 6.99,76.83 R131.1 R130.2
N15061: length 4.5
  TOP w0.381: U4.5 117.03,34.99 116.71,35.31 R16.2 R14.1 C27.2
N15235: length 6
  TOP w0.381: v1(113.35,34.99) U4.1
  BOTTOM w0.381: v1(113.35,34.99) 113.54,35.18 117.98,35.18
N17654: length 4.8
  TOP w0.381: U5.5 117.41,43.11 116.84,43.69 R26.2 R23.1 C36.2
N17828: length 6
  TOP w0.381: U5.1 v1(113.86,43.11)
  BOTTOM w0.381: v1(113.86,43.11) 113.92,43.18 C41.2 R25.2 R27.2 R24.2
N17964: length 10.6
  TOP w0.381: R23.2 C36.1 109.6,45.59 109.33,45.86 107.7,45.86 107.31,45.48 107.31,43.43
N20335: length 7.4
  TOP w0.381: R13.2 R10.2 119.76,50.16 119.38,50.55 R11.2 C23.2 116.46,50.55 115.76,49.84 U3.3
N28498: length 5.1
  TOP w0.381: R2.2 R4.2 C10.2 135.89,24.77 136.14,25.02 136.14,26.16 135.95,26.36 U1.4
N36801: length 1.8
  TOP w0.381: C24.1 110.81,49.84 U3.4
N41621: length 1.7
  BOTTOM w0.381: R18.2 120.07,32 119.81,32.26 D4.A
N41625: length 1.7
  BOTTOM w0.381: D5.A 118.85,45.97 R21.2
N052210: length 2.3
  BOTTOM w0.102: R78.2 45.34,69.27 Q1.1
N58665: length 25.7
  BOTTOM w0.381: R107.1 43.31,31.88 43.31,26.54 52.58,17.27 R103.1 C113.1 R102.2
N58697: length 17.5
  TOP w0.381: JP17.1 59.18,14.1 63.75,9.53 C108.1 J6.1
  BOTTOM w0.381: JP17.1 R102.1
N58961: length 5.2
  BOTTOM w0.381: U11.3 41.6,15.43 40.13,13.97 C118.2 R106.2 R105.2
N59213: length 8.4
  BOTTOM w0.201: JP17.3 50.16,14.1 C119.1 46.74,8.39 CN1.1
N59225: length 1.8
  BOTTOM w0.381: C115.1 41.6,19.75 U11.4
N071991: length 2.1
  BOTTOM w0.508: R101.1 106.55,69.43 Q4.3
N16425733: length 1.9
  BOTTOM w0.102: R179.2 58.29,75.46 J17.9
N16425793: length 1.9
  BOTTOM w0.102: J17.11 69.72,75.46 R176.2
N16425805: length 4.3
  BOTTOM w0.381: R95.1 C166.2 R92.1
N16425817: length 4.3
  TOP w0.102: U23.8 69.34,62.99 69.09,62.74 68.38,62.74 68.25,62.61 68.25,62.43 D24.A 68.25,61.77 68.25,61.29 R181.1
N16425841: length 4.3
  TOP w0.102: R178.1 67.89,61.29 67.89,61.77 D22.A 67.89,62.43 67.89,62.61 67.77,62.74 67.11,62.74 66.8,63.05 U23.6
N16425857: length 4.3
  TOP w0.102: U23.3 62.99,63.12 62.74,62.87 62,62.87 61.9,62.76 61.9,62.43 D21.A 61.9,61.77 61.9,61.29 R177.1
N16425869: length 4.3
  TOP w0.102: R174.1 61.54,61.29 61.54,61.77 D18.A 61.54,62.43 61.54,62.76 61.44,62.87 60.71,62.87 60.45,63.12 U23.1
N16426003: length 4.1
  TOP w0.381: U23.15 v1(61.72,71.22)
  BOTTOM w0.381: R92.2 62.08,70.87 v1(61.72,71.22) 60.24,71.22 D15.K
N16426121: length 4.2
  TOP w0.381: U23.10 v1(68.07,71.27)
  BOTTOM w0.381: D16.K 68.1,71.25 v1(68.07,71.27) 67.67,70.87 R95.2
N16457705: length 6.3
  TOP w0.178: v1(52.96,37.49) 53.16,37.7 U14.21 ; v1(57.99,46.58) 58.24,46.33 U14.78 ; U14.52 64.03,39.8 v1(64.03,39.8)
  TOP w0.508: v1(57.99,46.58) 57.99,47.07 v1(58.01,47.07)
  BOTTOM w0.305: C85.2 63.75,39.52 v1(64.03,39.8)
  BOTTOM w0.381: C83.2 53.88,37.11 53.34,37.11 v1(52.96,37.49)
N16486091: length 2.5
  BOTTOM w0.102: R48.1 JP3.3
N16486095: length 2.5
  BOTTOM w0.102: R47.1 JP3.1
N16486099: length 2.5
  BOTTOM w0.102: R46.1 JP2.3
N16486103: length 2.5
  BOTTOM w0.102: R45.1 JP2.1
N16486107: length 2.5
  BOTTOM w0.102: R43.1 JP1.3
N16486111: length 2.5
  BOTTOM w0.102: R42.1 JP1.1
N16486523: length 2.3
  TOP w0.178: U14.72 60.35,46.61 v1(60.08,46.88)
  BOTTOM w0.201: R49.1 60.07,46.61 60.07,46.84 60.1,46.86 60.1,46.88 v1(60.08,46.88)
N16520538: length 3.9
  BOTTOM w0.381: R61.2 82.16,32.77 D6.3
N16520613: length 4.6
  TOP w0.508: v1(86.87,34.8) 87.38,34.8 87.42,34.75 BT1.1
  BOTTOM w0.508: v1(86.87,34.8) 86.23,34.8 85.79,34.35 D6.1
N16568818: length 1.6
  TOP w0.102: U26.9 108.75,72.94 C187.1
N16568861: length 1.7
  TOP w0.102: C186.1 110.87,73.53 110.7,73.7 U26.12
N16569733: length 2.5
  TOP w0.102: U26.6 105.61,76.78 R209.2
N16569735: length 2.4
  TOP w0.102: R211.2 113.03,76.83 112.97,76.78 U26.15
N16571206: length 1.6
  TOP w0.102: U27.9 122.21,73.45 122.17,73.41 C182.1
N16571226: length 1.6
  TOP w0.102: C188.1 124.21,73.41 124.17,73.45 U27.12
N16571270: length 1.9
  TOP w0.102: U27.6 119.45,76.78 R208.2
N16571274: length 2.7
  TOP w0.102: R207.2 127.56,76.78 U27.15
N16589672: length 2.7
  TOP w0.102: v1(55.7,35.56) 55.79,35.65 U14.26
  BOTTOM w0.102: v1(55.7,35.56) 55.24,35.1 R203.2
N16609598: length 3.7
  TOP w0.102: U14.87 55.09,45.92 53.44,47.57 53.29,47.57 v1(53.26,47.6)
  BOTTOM w0.102: v1(53.26,47.6) 53.47,47.8 R204.2
N16674187: length 2.4
  TOP w0.102: J19.1 108.11,82.83 R150.2
N16674222: length 2.4
  TOP w0.102: J19.3 110.61,82.81 R151.2
N16674257: length 2.6
  TOP w0.102: R152.2 120.78,83.5 120.68,83.6 J20.1
N16674292: length 2.6
  TOP w0.102: R153.2 123.06,83.69 123.18,83.81 J20.3
N16750026: length 5.4
  TOP w0.508: v1(24.38,8.13) C72.2 C71.2 R91.1
  BOTTOM w0.508: U13.6 v1(24.38,8.13)
N16750096: length 4.8
  TOP w0.508: J5.1 v2(23.38,4.9)
  BOTTOM w0.508: R90.2 D7.A 22.86,5.45 23.38,4.93 v2(23.38,4.9)
N16750100: length 4.6
  TOP w0.508: J5.2 v2(24.63,4.88)
  BOTTOM w0.508: v2(24.63,4.88) 24.63,4.96 24.64,4.97 D25.K R94.2
N16750228: length 5.1
  BOTTOM w0.508: U13.2 23.11,14.61 23.37,14.35 24.13,14.35 24.38,14.61 U13.3 C59.2
N16750268: length 1.9
  BOTTOM w0.102: U13.1 R63.2
N16750308: length 2.8
  BOTTOM w0.102: R63.1 R60.1 R62.2
N16750370: length 4.5
  BOTTOM w0.201: R98.1 R93.2 25.65,14.61 U13.4
N16750378: length 1.4
  BOTTOM w0.201: R93.1 C73.2
N16750486: length 2.8
  BOTTOM w0.201: C146.1 JP23.3
N16751027: length 4.1
  BOTTOM w0.201: JP23.1 29.46,16.89 C73.1
N16751673: length 12.6
  BOTTOM w0.102: R62.1 23.24,21.59 32.26,21.59 JP20.2
N16764243: length 5.5
  TOP w0.508: U16.4 13.87,19.75 13.36,20.25 13.36,20.98 13.97,21.59 C87.1 R104.1 R108.2
N16764551:
  vias: v1(18.29,17.27) v1(18.8,17.27) v1(19.3,17.27)
N16771686: length 1.7
  BOTTOM w0.381: D11.A 141.3,41.94 R44.2
N16778150: length 4.5
  TOP w0.381: C66.2 R85.1 R88.2 116.71,28.7 117.03,28.38 U12.5
N16778213: length 5.8
  TOP w0.381: v1(113.35,28.38) U12.1
  BOTTOM w0.381: R86.2 R89.2 R87.2 C70.2 113.42,28.45 v1(113.35,28.38)
N16785770: length 3.8
  TOP w0.102: v1(52.07,42.93) 52.4,42.6 U14.7
  BOTTOM w0.102: v1(52.07,42.93) 52.45,42.93 R38.2
N16786493: length 6.1
  TOP w0.102: v1(50.77,42.32) 50.77,42.29 51.82,42.29 52.21,41.9 U14.9
  BOTTOM w0.102: R33.2 50.77,42.57 v1(50.77,42.32)
N16786550: length 5.3
  TOP w0.178: U14.20 52.83,38.05 v1(52.32,37.54)
  BOTTOM w0.381: v1(52.32,37.54) 52.32,36.83 C63.2 C47.2 R36.2
N16786676: length 4.8
  TOP w0.102: v1(60.91,35.08) 60.91,35.51 60.35,36.07 U14.39
  BOTTOM w0.305: 61.72,32.64 61.72,33.78 C45.2 C50.2 60.93,35.05 v1(60.91,35.08)
N16786698: length 2.9
  TOP w0.178: U14.38 60,36.02 60.38,35.64 v1(60.38,35.38)
  BOTTOM w0.381: v1(60.38,35.38) 61.32,36.32 C46.2
N16789313: length 2.6
  TOP w0.178: U14.66 63.44,44.7 63.63,44.88 v1(63.63,45.97)
  BOTTOM w0.201: R31.1 63.63,45.59 v1(63.63,45.97)
N16794051: length 6
  TOP w0.178: U14.61 64.54,42.95 64.82,43.23 64.97,43.23 v1(65,43.26)
  BOTTOM w0.305: v1(65,43.26) 65,43.26 65.25,43.26 65.68,43.69 C51.1 C49.1 68.45,43.69 R30.1
N16794071: length 6.2
  TOP w0.178: U14.63 63.89,43.65 64.9,44.65 v1(65.2,44.65)
  BOTTOM w0.305: v1(65.2,44.65) 65.86,44.65 C42.1 C43.1 R28.1
N16795142: length 5.1
  TOP w0.201: U14.16 51.87,39.45 51.28,38.86 v1(51.05,38.86)
  BOTTOM w0.201: v1(51.05,38.86) 51.18,38.86 51.31,38.99 C74.1 C75.1
N16795478: length 3.4
  TOP w0.178: U14.44 62.1,36.2 62.36,35.94 v1(63.25,35.94)
  BOTTOM w0.381: R37.2 C77.2 63.75,35.94 v1(63.25,35.94)
N16795922: length 6
  TOP w0.203: U7.1 62.23,21.69 C78.2 R40.2 R39.1
N16795926: length 2.7
  TOP w0.203: U7.3 63.37,22.55 C80.2 R41.1
N16800878: length 7.8
  TOP w0.178: U14.14 51.19,40.15 50.93,39.88 v1(50.67,39.88)
  BOTTOM w0.381: R32.1 46.61,39.5 C54.1 C53.1 49.4,39.5 49.78,39.88 v1(50.67,39.88)
N16800900: length 7.5
  TOP w0.178: U14.17 52.18,39.1 51.05,37.97 v1(50.67,37.97)
  BOTTOM w0.201: v1(50.67,37.97) 49.91,37.21 C55.1 48.32,36.51 47.94,36.51 C56.1
N16803827: length 3.1
  TOP w0.102: v1(58.37,35.46) 58.37,35.51 58.6,35.74 U14.34
  BOTTOM w0.102: RR3.2 58.55,35.99 58.37,35.81 v1(58.37,35.46)
N16803833: length 4
  TOP w0.102: U14.35 58.95,35.22 58.88,35.15 v1(58.88,35.1)
  BOTTOM w0.102: RR2.2 58.88,36.65 v1(58.88,35.1)
N16837752: length 5.8
  TOP w0.178: U14.73 60,46.18 59.65,46.53 59.65,47.35 v1(59.72,47.42)
  BOTTOM w0.381: R97.1 60.58,49.91 C124.1 C125.1 60.2,48.13 59.72,47.65 v1(59.72,47.42)
N16837764: length 5.9
  TOP w0.178: U14.71 60.7,46.9 60.72,46.93 v1(60.72,47.03)
  BOTTOM w0.381: R96.1 61.85,49.91 C123.1 C122.1 61.47,47.57 60.92,47.03 v1(60.72,47.03)

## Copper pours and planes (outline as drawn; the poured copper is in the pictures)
D0.9V on VCC: 61.9,44.4 63.82,42.48 97.28,42.48 98.23,43.43 99.95,43.43 100.2,43.18 100.2,39.24 99.82,38.86 92.84,38.86 91.26,40.44 63.78,40.44 63.22,39.88 63.22,39.5 62.53,38.81 62.53,38.79 60.95,37.2 55.66,37.2 54.48,38.38 54.48,38.61 54.61,38.73 56.01,38.73 56.24,38.51 60.45,38.51 60.73,38.79 60.73,42.88 60.44,43.17 57.8,43.17 57.51,43.46 57.51,44.73 57.63,44.86 59.87,44.86 60.33,44.4
D1.8V on VCC: 43.03,55.78 44.93,55.78 45.54,56.39 49.91,56.39 50.52,55.78 52.7,55.78 56.71,51.78 59.26,51.78 59.49,51.55 59.49,47.22 59.99,46.71 59.99,46.58 60.35,46.23 63.02,46.23 63.5,45.75 74.93,45.75 79.48,50.29 99.31,50.29 99.95,49.66 99.95,44.96 99.06,44.07 62.94,44.07 62.15,44.86 59.54,44.86 58.55,45.85 58.55,47.37 58.04,47.88 57.63,47.88 57.07,48.44 57.07,49.1 53.85,52.32 51.84,52.32 49.78,54.38 43.61,54.38 43.03,53.8 43.03,52.65 42.29,51.92 41.43,51.92 41.15,52.2 41.15,53.82 41.71,54.38 41.71,54.46
D3.3V on VCC (solid shape): outline of 175 points within 123.24,46.35 153.57,77.11
D3.3V on BOTTOM: 57.4,52.58 58.12,52.58 58.24,52.45 58.24,49.35 58.17,49.28 57.38,49.28 57.28,49.38 57.28,52.45
D3.3V on VCC: 55.5,56.13 77.72,56.13 79.12,54.74 97.66,54.74 99.44,56.52 99.44,66.67 99.82,67.06 100.46,67.06 100.97,66.55 100.97,51.69 100.71,51.44 78.23,51.44 72.64,45.85 69.16,45.85 68.94,46.08 64.77,46.08 63.17,47.68 63.17,51.38 62.48,52.07 57.15,52.07 53.19,56.03 51.05,56.03 50.09,57 45.39,57 44.42,56.03 24.89,56.03 24.77,56.16 24.77,57.02 25.04,57.3 41.68,57.3 41.71,57.33 41.73,57.3 43.76,57.3 45.53,59.07 46.34,59.07 46.61,59.33 46.61,62.87 47.31,63.56 48.07,63.56
D5.0V on TOP: 133.28,40.77 127.94,40.77 127.81,40.89 127.81,42.16 127.94,42.29 128.7,42.29 128.96,42.04 133.28,42.04 133.4,41.91 133.4,40.89
D5.0V on TOP: 117.22,41.53 122.56,41.53 122.68,41.4 122.68,40.01 122.56,39.88 117.35,39.88 117.09,40.13 117.09,41.4
D5.0V on TOP: 114.17,48.26 119.63,48.26 119.76,48.13 119.76,47.12 119.63,46.99 114.3,46.99 114.05,47.24 114.05,48.13
D5.0V on TOP: 123.49,35.86 125.07,35.86 125.37,35.56 125.37,32.38 125.02,32.03 123.57,32.03 123.22,32.38 123.22,35.59
D5.0V on TOP: 116.71,33.4 122.05,33.4 122.17,33.27 122.17,31.88 122.05,31.75 116.84,31.75 116.59,32 116.59,33.27
D5.0V on BOTTOM: 11.43,53.72 11.43,56.13 11.56,56.26 12.95,56.26 13.08,56.13 13.08,53.59 12.95,53.47 11.68,53.47
D5.0V on BOTTOM: 104.57,70.82 104.5,70.74 101.22,70.74 100.84,71.12 100.84,73.15 100.97,73.28 102.36,73.28 103,73.91 103.94,73.91 104.57,73.28
D5.0V on VCC: 43.51,11.71 44.55,11.71 44.7,11.56 44.7,9.88 44.63,9.8 43.59,9.8 43.41,9.98 43.41,11.61
D5.0V on VCC: 118.59,44.88 118.21,45.26 118.21,47.75 118.75,48.29 120.57,48.29 123.23,45.62 129.55,45.62 131.55,47.62 149.25,47.62 154.43,52.81 154.43,78.49 149.1,83.82 118.85,83.82 118.14,83.11 118.14,80.34 117.81,80.01 116.43,80.01 116.18,80.26 116.18,83.26 115.62,83.82 108.89,83.82 104.39,79.32 104.39,71.5 104.01,71.12 101.47,71.12 101.47,80.01 107.19,85.72 150.5,85.72 156.59,79.63 156.59,51.05 150.37,44.83 139.09,44.83 138.84,44.58 138.84,42.8 139.45,42.19 139.45,41.96 139.17,41.68 129.59,41.68 125.48,37.57 125.48,26.72 124.03,25.27 121.16,25.27 121.01,25.43 121.01,43.99 120.12,44.88
D5.0V on VCC: 11.3,56.44 13.13,56.44 13.23,56.34 13.23,55.35 13.03,55.14 11.33,55.14 11.25,55.22 11.25,56.39
D12V on BOTTOM (solid shape): 13.62,19.2 13.64,19.2 13.65,19.19 13.7,19.14 13.71,19.12 13.72,19.11 13.72,16.99 13.71,16.97 13.7,16.95 13.63,16.88 13.61,16.87 13.59,16.87 9.47,16.87 8.39,17.95 8.39,19.04 8.54,19.19 8.65,19.19 8.66,19.2 8.68,19.2
D12V on TOP: 136.27,27.69 137.16,28.57 139.57,28.57 140.08,29.08 140.08,30.23 140.31,30.45 142.16,30.45 142.44,30.18 142.44,27.05 142.32,26.92 134.81,26.92 134.75,26.98 134.75,27.63 134.8,27.69
D12V on VCC: 136.78,28.88 140.08,28.88 140.46,28.5 140.46,26.8 139.88,26.21 137.26,26.21 134.9,23.85 134.9,12.47 131.22,8.79 125.45,8.79 123.36,6.69 109.92,6.69 104.7,1.47 84.49,1.47 83.77,2.2 83.73,2.2 79.32,6.6 61.77,6.6 59.41,4.24 30.15,4.24 27.43,1.52 14.66,1.52 8,8.18 8,18.92 8.38,19.3 9.91,19.3 10.03,19.18 10.03,9.3 16.31,3.02 26.44,3.02 29.01,5.59 58.39,5.59 60.81,8 80.31,8 85.39,2.92 103.23,2.92 109.09,8.79 122.07,8.79 124.03,10.74 128.93,10.74 132.05,13.87 132.05,24.16
GND on TOP (solid shape): 6.63,83.29 0.81,83.29 0.81,88.11 1.91,89.2 6.63,89.2
GND on TOP (solid shape): 159.16,2.01 157.99,0.84 153.26,0.84 153.26,6.76 159.16,6.76
GND on TOP (solid shape): 159.18,88.06 159.18,83.34 153.26,83.34 153.26,89.24 158.01,89.24
GND on TOP (solid shape): 6.71,0.97 6.5,0.76 2.34,0.76 0.79,2.31 0.79,7.04 6.71,7.04
GND on BOTTOM (solid shape): 6.63,83.29 0.81,83.29 0.81,88.11 1.91,89.2 6.63,89.2
GND on BOTTOM (solid shape): 159.16,2.01 157.99,0.84 153.26,0.84 153.26,6.76 159.16,6.76
GND on BOTTOM (solid shape): 159.18,88.06 159.18,83.34 153.26,83.34 153.26,89.24 158.01,89.24
GND on BOTTOM (solid shape): 6.71,0.97 6.5,0.76 2.34,0.76 0.79,2.31 0.79,7.04 6.71,7.04
GND on VCC (solid shape): 6.63,83.29 0.81,83.29 0.81,88.11 1.91,89.2 6.63,89.2
GND on VCC (solid shape): 159.16,2.01 157.99,0.84 153.26,0.84 153.26,6.76 159.16,6.76
GND on VCC (solid shape): 159.18,88.06 159.18,83.34 153.26,83.34 153.26,89.24 158.01,89.24
GND on VCC (solid shape): 81.05,4.55 81.05,0.79 74.63,0.79 74.63,5.94 75.01,6.32 79.27,6.32
GND on VCC (solid shape): 6.71,0.97 6.5,0.76 2.34,0.76 0.79,2.31 0.79,7.04 6.71,7.04
GND on TOP: 2.34,0.76 0.76,2.34 0.76,88.12 1.88,89.24 158.06,89.24 159.24,88.06 159.24,2.06 157.94,0.76 22.1,0.76 19.43,0.76 19.43,0.76 ; 37 cut-outs
GND on BOTTOM: 2.34,0.76 0.76,2.34 0.76,88.12 1.88,89.24 158.06,89.24 159.24,88.06 159.24,2.06 157.94,0.76 ; 13 cut-outs
GND on GND: 2.34,0.76 0.76,2.34 0.76,88.12 1.88,89.24 158.06,89.24 159.24,88.06 159.24,2.06 157.94,0.76 ; 1 cut-out
GND on VCC: 2.34,0.76 0.76,2.34 0.76,88.12 1.88,89.24 158.06,89.24 159.24,88.06 159.24,2.06 157.94,0.76 ; 2 cut-outs
VBUS on TOP: 94.77,73.76 93.73,73.76 93.6,73.89 93.6,77.9 93.71,78.02 94.78,78.02 94.92,77.88 94.92,73.91
VBUS on BOTTOM: 96.27,77.6 96.27,74.8 95.76,74.3 93.47,74.3 93.34,74.42 93.34,77.85 93.47,77.98 95.89,77.98
DDR_D1.35V on TOP (solid shape): 110.62,29.25 110.64,29.24 110.64,29.22 110.64,25.84 110.48,25.67 110.46,25.66 110.44,25.65 109.41,25.65 109.38,25.67 107.85,27.2 107.83,27.21 107.81,27.22 101.22,27.22 100.85,27.57 100.84,27.59 100.84,27.61 100.84,28.81 100.84,28.83 100.85,28.84 101.39,29.39 101.41,29.4 101.43,29.4 110.47,29.4
DDR_IO on BOTTOM (solid shape): 57.93,36.31 57.93,35.16 58.17,34.92 58.17,33.15 58.04,33.02 57.53,33.02 57.31,33.24 57.31,33.71 57.06,33.96 57.06,36.41 57.1,36.45 57.78,36.45
DDR_IO on BOTTOM (solid shape): 60.17,35.03 60.17,34.75 60.1,34.67 60.1,33.35 60.05,33.3 59.79,33.3 59.69,33.4 59.08,33.4 59.03,33.45 59.03,34.62 59.26,34.85 59.26,35.03 59.39,35.15 60.05,35.15
DDR_IO on VCC: 58.01,35.21 58.34,34.87 59.03,34.87 59.36,35.2 59.69,35.2 59.69,35.2 59.98,35.2 60.18,35 60.18,34.38 59.97,34.17 59.97,32.21 63.14,29.03 63.8,29.03 66.97,25.87 89.97,25.87 96.1,32 102.49,32 102.87,31.62 102.87,30.48 102.11,29.72 97.66,29.72 92.2,24.26 65.15,24.26 57.38,32.02 57.38,35.39 57.48,35.49 57.9,35.49 58.01,35.38
IRLED- on TOP (solid shape): 14.71,9.19 14.71,1.74 14.58,1.62 13.67,1.62 13.65,1.62 13.63,1.63 13.6,1.68 13.6,8.19 13.6,8.19 13.6,9.3 13.64,9.36 13.65,9.37 13.67,9.37 14.53,9.37
MIPI_D5.0V on BOTTOM (solid shape): 15.24,54.43 15.24,52.64 15.11,52.51 13.84,52.51 13.64,52.72 13.64,54.42 13.78,54.56 15.1,54.56
MIPI_D5.0V on TOP: 10.97,52.72 10.97,53.02 11.2,53.25 15.01,53.25 15.16,53.1 15.16,52.64 14.88,52.36 13.64,52.36 13.44,52.57 11.13,52.57
VM on BOTTOM (solid shape): 117.94,76.85 117.95,76.83 117.96,76.81 117.96,74.96 117.79,74.79 116.17,74.79 116.08,74.88 116.08,76.9 116.14,76.97 116.16,76.98 116.18,76.99 117.79,76.99
VM on VCC: 127.76,71.5 109.6,71.5 106.83,74.27 105.45,74.27 105.17,74.55 105.17,75.2 105.41,75.44 127.64,75.44 128.14,74.93 128.14,71.88
N07819 on BOTTOM: 96.65,76.45 104.8,76.45 104.85,76.4 104.85,74.35 104.8,74.3 96.77,74.3 96.52,74.55 96.52,76.33
N08066 on TOP: 154.81,26.42 154.81,15.24 153.92,14.35 146.69,14.35 145.16,12.83 141.41,12.83 140.91,13.34 140.91,15.27 141.59,15.95 141.59,21.2 147.5,27.1 154.13,27.1
N08150 on TOP: 155.32,35.05 155.32,31.82 154.93,31.42 144.08,31.42 142.92,32.58 140.35,32.58 140.21,32.72 140.21,35.05 140.72,35.56 154.81,35.56
N09840 on TOP: 136.14,34.54 136.27,34.42 136.27,28.19 136.02,27.94 134.49,27.94 134.37,28.07 134.37,34.42 134.49,34.54
N09899 on TOP: 126.72,34.67 132.46,34.67 132.59,34.54 132.59,30.86 132.46,30.73 126.49,30.73 126.31,30.91 126.31,34.26
N12312 on TOP: 136.32,41.15 136.2,41.02 134.67,41.02 134.67,42.44 134.77,42.54 134.77,46.53 134.85,46.61 136.2,46.61 136.32,46.48
N12324 on TOP: 133.91,46.48 133.91,43.43 133.66,43.18 132.64,43.18 132.39,43.43 132.39,44.02 132.13,44.27 127.41,44.27 127.37,44.31 126.63,44.31 126.24,44.7 126.24,47.88 126.49,48.13 132.72,48.13 133.78,47.06 133.78,46.61
N15383 on TOP: 115.19,32 109.6,32 109.22,32.38 109.22,33.53 109.47,33.78 112.9,33.78 113.28,33.4 115.32,33.4 115.32,32.13
N17960 on TOP: 115.95,41.53 116.08,41.4 116.08,40.01 115.95,39.88 112.39,39.88 112.39,39.88 112.23,39.88 112.16,39.95 112.16,43.63 112.22,43.69 113.28,43.69 113.41,43.56 113.41,42.11 114,41.53
N17964 on TOP: 110.36,43.69 110.36,39.5 109.98,39.12 100.97,39.12 100.84,39.24 100.84,43.56 100.97,43.69
N20515 on TOP: 112.9,48.26 113.03,48.13 113.03,47.12 112.9,46.99 101.22,46.99 100.84,47.37 100.84,49.02 100.97,49.15 102.87,49.15 103.76,48.26
N16457705 on BOTTOM: 58.42,46.69 58.06,46.33 57.86,46.33 57.76,46.43 57.07,46.43 56.9,46.61 56.9,46.91 57.38,47.4 57.38,48.54 57.43,48.59 58.29,48.59 58.42,48.46
N16457705 on VCC: 54.24,41.95 54.24,38.01 55.31,36.94 61.18,36.94 63.68,39.45 63.68,39.98 63.83,40.13 65.15,40.13 65.43,39.85 65.43,39.12 62.46,36.14 53.95,36.14 52.7,37.39 52.7,42.27 57.28,46.84 57.28,47.24 57.4,47.37 58.17,47.37 58.29,47.24 58.29,46
N16778255 on TOP (solid shape): 112.78,29.19 112.8,29.18 112.81,29.17 112.89,29.1 112.9,29.08 112.9,29.06 112.9,27.2 112.91,27.18 112.92,27.16 113.27,26.81 113.29,26.8 113.31,26.8 115.27,26.8 115.3,26.78 115.32,26.75 115.32,25.8 115.31,25.78 115.3,25.77 115.2,25.67 115.19,25.66 115.17,25.65 111.78,25.65 111.76,25.66 111.75,25.67 111.63,25.78 111.61,25.81 111.61,25.83 111.61,29.07 111.61,29.09 111.62,29.11 111.69,29.17 111.71,29.18 111.73,29.19

Small or netless copper shapes (teardrops, artwork), in the pictures only: 8 on TOP, 3 on BOTTOM

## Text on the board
Ref Des/Silkscreen Top: BOOT | MODE | SEL1 | SEL0 | MOT_OUT2 | MOT_OUT3 | MOT_OUT4 | MOT_OUT5 | MOT_OUT6 | MOT_OUT7 | MOT_OUT8 | MOT_OUT9 | IRCUT | 1 | 2 | 3 | 4 | CLK | SCL | SDA | VS | HS | RST | ARTWORK TOP | PLANE GND | PLANE VCC | ARTWORK BOTTOM | GND | IR_LED_IN | CDS2 | CDS1 | LED+ | DN0 | CKN | CKP | DP0 | DN1 | DP1 | LED- | BOOT_MODE | 0 | BOOT_SEL1 | SPK | X | AC-OUTL | BOOT_SEL0 | Nor Flash | Uart Download | SD0 Emmc | Nand Flash | SD1 Emmc | AUDIO-EN | LINE-OUT | LINE-IN | AC-MICIP3 | MIC | SPI0 | NOR | NAND | DDR_1.35V | DDR_1.8V | DDR_IO | D1.8V | D0.9V | IR_OFF | RX1 | RX0 | PWM9 | TX1 | TX0 | PWM8 | D3.3V | D5.0V | PWM7 | PWM6 | SRSTN | DBGRQ | TDI | TMS | TCK | RTCK | TDO | TRSTN | OFF | ON | AD1 | AD0 | DATA2 | DATA3 | CMD | CD | 3.3V | DATA0 | DATA1 | G_28 | ETH_ACT | SD_EN | PWM11 | CH-U1-RX | U1-RX | USB | MOTO | G_4 | G_3 | G_2 | G_1 | G_0 | SD0 | ZTV2-QFN88_APP_SOCKET_BOARD_L4_V1 | 2021-06-25 | F660614 | GPIO_ | RESET | 12V_IN
DEVICE_TYPE_TOP: 1.27 | 3.81 | 45.72 | 50.5 | 55.4 | 30 | 7.4 | 4.85 | 20.32 | 16 | USR-TCP232-E
